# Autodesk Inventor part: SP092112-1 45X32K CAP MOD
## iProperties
Created: 2007-01
Part Number: SP092112-1 45X32K CAP MOD
Document SubType Name: Modeling
Designer: Andy Moles
Material: ABS Plastic
Density: 1.06 g/cm^3
Mass: 4.46297 g
Surface Area: 35.8055 cm^2
Volume: 4.21035 cm^3
Author: Andy Moles
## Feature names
1. Extrusion1
2. Fillet1
3. Fillet2
4. Extrusion2
5. Extrusion3
6. Fillet3
7. Extrusion4
8. Fillet4
9. Extrusion5
10. Fillet5
